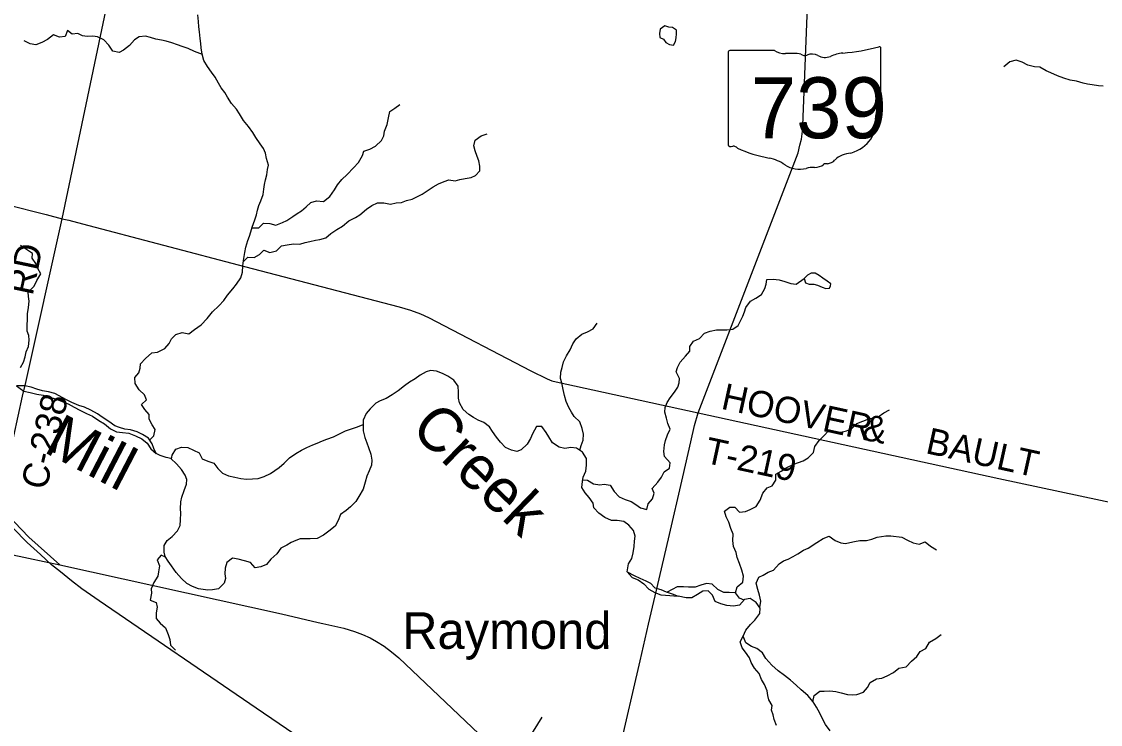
# Model space of a CAD drawing. Extents: x 0 to 34, y 0 to 22.
# Drawn here: x 4.289 to 5.454, y 16.008 to 16.767 of the extents above; entities that cross this region are included whole.
import ezdxf

# ---------------------------------------------------------------- set-up
doc = ezdxf.new("R2010")
doc.units = 0
for name, color, linetype in [('GM_X_County_Road', 7, 'Continuous'), ('GM_X_County_Road_Text', 7, 'Continuous'), ('GM_X_Minor_Lake', 7, 'Continuous'), ('GM_X_Minor_River', 7, 'Continuous'), ('GM_X_Minor_River_Text', 7, 'Continuous'), ('GM_X_Rail_Line', 7, 'Continuous'), ('GM_X_State_Location', 7, 'Continuous'), ('GM_X_State_Route', 7, 'Continuous'), ('GM_X_State_Shield', 7, 'Continuous'), ('GM_X_Township_Road', 7, 'Continuous'), ('GM_X_Township_Road_Text', 7, 'Continuous'), ('GM_X_Unincorporated_Text', 7, 'Continuous')]:
    doc.layers.add(name, color=color, linetype=linetype)

msp = doc.modelspace()

# ---------------------------------------------------------------- linework, layer by layer
at = {"layer": 'GM_X_County_Road'}
msp.add_line((4.2903, 16.3625), (4.2936, 16.3773), dxfattribs=at)
for points in [[(4.2936, 16.3773), (4.333, 16.5543), (4.4295, 17.0147), (4.5014, 17.3574)], [(4.2728, 16.5698), (4.3156, 16.5588), (4.333, 16.5543), (4.3403, 16.5528), (4.3548, 16.5489), (4.5299, 16.5028), (4.697, 16.459), (4.7091, 16.4555), (4.7198, 16.4517), (4.7285, 16.4476), (4.8392, 16.3899), (4.8569, 16.3811), (4.8619, 16.3792), (4.8666, 16.3781), (5.02, 16.3446)], [(4.3303, 16.1801), (4.2971, 16.2101), (4.2816, 16.2262), (4.2729, 16.236), (4.2689, 16.2412), (4.2665, 16.2462), (4.2657, 16.2525), (4.2662, 16.2589), (4.2807, 16.3193), (4.2903, 16.3625)]]:
    msp.add_lwpolyline(points, dxfattribs=at)
at = {"layer": 'GM_X_Minor_Lake'}
for points in [[(4.9787, 16.7593), (4.9781, 16.7547), (4.9785, 16.7504), (4.9824, 16.7486), (4.9849, 16.7448), (4.989, 16.7426), (4.9932, 16.7418), (4.9955, 16.7458), (4.9961, 16.7497), (4.9965, 16.7541), (4.9965, 16.7556)], [(4.9965, 16.7556), (4.9965, 16.7581), (4.9921, 16.7609), (4.988, 16.7615), (4.9838, 16.7629), (4.9787, 16.7593)], [(5.1626, 16.4819), (5.1632, 16.4838), (5.1593, 16.4867), (5.1544, 16.4901), (5.1506, 16.4931), (5.1462, 16.4956), (5.1419, 16.4954), (5.1379, 16.4932), (5.1343, 16.4896)], [(5.1343, 16.4896), (5.1358, 16.4852), (5.1398, 16.4837), (5.1447, 16.4837), (5.1487, 16.4825), (5.1536, 16.4802), (5.1577, 16.4789), (5.1617, 16.4794), (5.1626, 16.4819)]]:
    msp.add_lwpolyline(points, dxfattribs=at)
at = {"layer": 'GM_X_Minor_River'}
for points in [[(4.4274, 16.3151), (4.432, 16.3198), (4.4335, 16.3264), (4.4301, 16.3315), (4.4271, 16.3378), (4.4269, 16.3427), (4.4224, 16.3481), (4.4187, 16.3536), (4.4242, 16.3587), (4.4219, 16.3638), (4.4163, 16.3693), (4.4119, 16.3762), (4.4114, 16.3826), (4.4156, 16.3879), (4.4171, 16.3927), (4.4177, 16.3974), (4.4228, 16.4034), (4.4297, 16.4095), (4.4361, 16.41), (4.4437, 16.414), (4.4486, 16.4195), (4.4509, 16.4244), (4.4557, 16.4291), (4.4627, 16.4312), (4.4697, 16.4298), (4.4758, 16.4347), (4.4832, 16.4396), (4.4897, 16.4464), (4.4952, 16.4538), (4.502, 16.4601), (4.5076, 16.4661), (4.5116, 16.4716), (4.5173, 16.4786), (4.5213, 16.4835), (4.5258, 16.4903), (4.5276, 16.4967), (4.528, 16.5034), (4.5288, 16.5093), (4.5301, 16.5178), (4.5315, 16.5237), (4.5336, 16.5309), (4.5353, 16.5356), (4.5366, 16.5403), (4.5382, 16.5453), (4.5412, 16.5532), (4.543, 16.5587), (4.5439, 16.5636), (4.5455, 16.5686), (4.5476, 16.5735), (4.5499, 16.5807), (4.5508, 16.5864), (4.5516, 16.5915), (4.5524, 16.5964), (4.5539, 16.6019), (4.5549, 16.6074), (4.5557, 16.6123), (4.5538, 16.6194), (4.5525, 16.6252), (4.5504, 16.6304), (4.5467, 16.6353), (4.5421, 16.642), (4.539, 16.6475), (4.5342, 16.654), (4.5288, 16.6606), (4.5246, 16.6676), (4.5211, 16.6726), (4.5158, 16.6789), (4.5114, 16.6857), (4.5086, 16.6907), (4.5047, 16.6958), (4.5018, 16.7009), (4.4983, 16.7072), (4.4941, 16.7127), (4.49, 16.7188), (4.4858, 16.7254), (4.4843, 16.7323), (4.4832, 16.7391), (4.4829, 16.7439), (4.4821, 16.7492), (4.4812, 16.7562), (4.4805, 16.7619), (4.4801, 16.7674), (4.4796, 16.7746)], [(4.4845, 16.7317), (4.476, 16.7352), (4.469, 16.7382), (4.4626, 16.7405), (4.4575, 16.7422), (4.4514, 16.7445), (4.4454, 16.7463), (4.4401, 16.7472), (4.4342, 16.7484), (4.4283, 16.7501), (4.4229, 16.7515), (4.416, 16.7509), (4.4111, 16.7477), (4.4056, 16.7415), (4.3991, 16.7366), (4.3944, 16.7341), (4.3876, 16.7355), (4.3834, 16.7418), (4.3778, 16.7477), (4.3713, 16.7511), (4.366, 16.7517), (4.3598, 16.7513), (4.3549, 16.7519), (4.3499, 16.7544), (4.3439, 16.7537), (4.3388, 16.7579), (4.3361, 16.7514), (4.3302, 16.7507), (4.3236, 16.7532), (4.3171, 16.7481), (4.3109, 16.7447), (4.3044, 16.7424), (4.2984, 16.7434), (4.2921, 16.7465)], [(5.4573, 16.6975), (5.4524, 16.6979), (5.4454, 16.6991), (5.4405, 16.6998), (5.4355, 16.7008), (5.4285, 16.7029), (5.4217, 16.7041), (5.4147, 16.7064), (5.4081, 16.7089), (5.4007, 16.7119), (5.3956, 16.7142), (5.3888, 16.7182), (5.383, 16.7184), (5.376, 16.7203), (5.3697, 16.7234), (5.3633, 16.7259), (5.3565, 16.724), (5.35, 16.7185)], [(4.5379, 16.5444), (4.5452, 16.5445), (4.5503, 16.5494), (4.5571, 16.549), (4.5639, 16.5473), (4.571, 16.5503), (4.5757, 16.5523), (4.582, 16.5567), (4.5867, 16.5599), (4.5915, 16.5627), (4.5964, 16.5672), (4.6015, 16.572), (4.6078, 16.5736), (4.6152, 16.573), (4.6222, 16.5783), (4.6272, 16.5855), (4.6302, 16.591), (4.635, 16.5969), (4.6407, 16.6023), (4.6477, 16.6095), (4.6531, 16.6152), (4.6574, 16.6226), (4.6586, 16.6275), (4.6654, 16.6294), (4.6715, 16.6328), (4.6778, 16.639), (4.6804, 16.6441), (4.6812, 16.649), (4.6841, 16.6562), (4.6854, 16.6634), (4.6868, 16.6701), (4.6921, 16.6738), (4.6978, 16.6778)], [(4.5285, 16.5077), (4.5335, 16.5127), (4.5403, 16.5124), (4.5462, 16.5155), (4.5508, 16.5204), (4.5574, 16.5177), (4.5644, 16.5196), (4.5697, 16.5252), (4.5758, 16.5262), (4.5828, 16.5271), (4.5896, 16.5269), (4.5955, 16.5287), (4.6004, 16.5299), (4.6065, 16.5312), (4.6112, 16.5319), (4.6177, 16.5336), (4.6232, 16.5385), (4.6297, 16.5428), (4.6357, 16.5462), (4.6426, 16.5519), (4.6496, 16.5555), (4.6543, 16.5587), (4.6616, 16.5645), (4.6673, 16.5687), (4.6735, 16.5715), (4.6803, 16.5715), (4.6874, 16.5701), (4.6938, 16.5714), (4.6993, 16.572), (4.7048, 16.5739), (4.7111, 16.5753), (4.7169, 16.5782), (4.7217, 16.581), (4.7281, 16.5851), (4.7336, 16.5889), (4.7393, 16.5919), (4.7456, 16.5946), (4.7507, 16.5963), (4.7575, 16.5953), (4.7623, 16.5968), (4.7683, 16.5977), (4.7746, 16.599), (4.7795, 16.6009), (4.7841, 16.606), (4.7841, 16.6111), (4.7828, 16.6168), (4.7813, 16.6216), (4.7789, 16.6278), (4.7774, 16.6331), (4.7789, 16.6394), (4.7854, 16.6439), (4.7918, 16.646)], [(4.2881, 16.3935), (4.2912, 16.3992), (4.2929, 16.4051), (4.294, 16.4104), (4.2965, 16.4164), (4.2975, 16.4231), (4.2968, 16.428), (4.2951, 16.4327), (4.2953, 16.4388), (4.2957, 16.4456), (4.2955, 16.4517), (4.2965, 16.4585), (4.2975, 16.4654), (4.2967, 16.4701), (4.2964, 16.475), (4.3028, 16.4815), (4.3057, 16.4877), (4.3101, 16.4949), (4.3067, 16.5006), (4.3045, 16.5061), (4.3005, 16.5116), (4.3011, 16.5166), (4.288, 16.5253)], [(4.8952, 16.2721), (4.9004, 16.2718), (4.9067, 16.2679), (4.9135, 16.2668), (4.9184, 16.2675), (4.9247, 16.2662), (4.9292, 16.2595), (4.9345, 16.2538), (4.9409, 16.2509), (4.9475, 16.2488), (4.9526, 16.2454), (4.9577, 16.2418), (4.9643, 16.2399), (4.9657, 16.2461), (4.9706, 16.2516), (4.9722, 16.2578), (4.9703, 16.2628), (4.9762, 16.2694), (4.9802, 16.2751), (4.9831, 16.2809), (4.9888, 16.2847), (4.9895, 16.2904), (4.9835, 16.2973), (4.9828, 16.3028), (4.9836, 16.3098), (4.9847, 16.3145), (4.9866, 16.3206), (4.9895, 16.3268), (4.9871, 16.3329), (4.9858, 16.3388), (4.9837, 16.3452), (4.9841, 16.3504), (4.9862, 16.3558), (4.9896, 16.3608), (4.9942, 16.367), (4.9978, 16.3721), (4.9994, 16.3769), (4.9996, 16.3818), (4.9962, 16.3888), (4.9975, 16.3937), (5.0004, 16.3992), (5.0061, 16.4057), (5.0107, 16.4113), (5.0107, 16.4163), (5.0149, 16.4219), (5.0213, 16.4249), (5.0268, 16.4308), (5.0329, 16.4329), (5.0395, 16.4342), (5.0443, 16.4343), (5.0507, 16.4341), (5.0574, 16.4349), (5.0631, 16.439), (5.0657, 16.4439), (5.0682, 16.4491), (5.0699, 16.4538), (5.0713, 16.4585), (5.0764, 16.4651), (5.0823, 16.4683), (5.0882, 16.4725), (5.092, 16.4789), (5.0932, 16.4837), (5.0941, 16.4888), (5.1009, 16.4891), (5.1072, 16.4882), (5.1134, 16.4864), (5.1201, 16.4843), (5.1257, 16.4837), (5.1343, 16.4896)], [(4.8919, 16.3041), (4.8936, 16.3092), (4.8957, 16.3148), (4.8959, 16.3215), (4.8944, 16.3277), (4.8922, 16.3348), (4.8861, 16.3407), (4.8831, 16.3454), (4.8803, 16.3502), (4.8773, 16.3568), (4.8754, 16.3633), (4.8741, 16.3699), (4.8726, 16.3769), (4.8713, 16.3817), (4.8717, 16.3885), (4.8731, 16.3934), (4.8744, 16.3997), (4.8778, 16.4061), (4.8815, 16.4127), (4.8845, 16.4192), (4.888, 16.4245), (4.8942, 16.4294), (4.9005, 16.432), (4.9064, 16.4354), (4.9108, 16.4413)], [(4.9432, 16.1726), (4.9445, 16.1812), (4.9482, 16.1871), (4.9495, 16.1933), (4.9507, 16.1999), (4.9511, 16.2058), (4.9517, 16.2111), (4.9499, 16.2172), (4.945, 16.2231), (4.9395, 16.2269), (4.9325, 16.2281), (4.9261, 16.2281), (4.9189, 16.2314), (4.9127, 16.2362), (4.9072, 16.2419), (4.9063, 16.2468), (4.9021, 16.2531), (4.8978, 16.2579), (4.8943, 16.2638), (4.8949, 16.2702), (4.8956, 16.2751), (4.8985, 16.2816), (4.8993, 16.288), (4.8992, 16.2952), (4.895, 16.3019), (4.8886, 16.3063), (4.8824, 16.3069), (4.8759, 16.3058), (4.8697, 16.3075), (4.8625, 16.3121), (4.8584, 16.3184), (4.8556, 16.3232), (4.8509, 16.3296), (4.8452, 16.3297), (4.841, 16.3217), (4.8389, 16.3168), (4.8352, 16.3106), (4.8288, 16.3047), (4.824, 16.3028), (4.8181, 16.304), (4.8119, 16.3071), (4.8065, 16.3128), (4.8021, 16.3181), (4.7976, 16.3244), (4.7944, 16.3294), (4.7882, 16.334), (4.7822, 16.3365), (4.7772, 16.3393), (4.7723, 16.3426), (4.7659, 16.3481), (4.7622, 16.3555), (4.7611, 16.3605), (4.7609, 16.3667), (4.7606, 16.3734), (4.7561, 16.3798), (4.7495, 16.384), (4.7436, 16.3871), (4.7374, 16.3896), (4.7309, 16.3904), (4.7262, 16.3887), (4.7195, 16.3852), (4.7142, 16.3812), (4.7081, 16.3776), (4.7028, 16.3737), (4.696, 16.3684), (4.6893, 16.3641), (4.683, 16.3601), (4.6764, 16.3575), (4.6716, 16.3551), (4.6655, 16.349), (4.6614, 16.3439), (4.6581, 16.3367), (4.6581, 16.3305), (4.6582, 16.3252), (4.6597, 16.318), (4.6619, 16.3121), (4.6638, 16.3069), (4.6664, 16.2999), (4.6673, 16.2935), (4.6671, 16.288), (4.6646, 16.2819), (4.6619, 16.276), (4.6602, 16.2696), (4.6579, 16.262), (4.6533, 16.2541), (4.65, 16.2488), (4.6445, 16.2428), (4.6397, 16.239), (4.6336, 16.2345), (4.6311, 16.228), (4.6277, 16.222), (4.6209, 16.2165), (4.6153, 16.2124), (4.6085, 16.2088), (4.6009, 16.2083), (4.5951, 16.2085), (4.5901, 16.2082), (4.5852, 16.2067), (4.5804, 16.2044), (4.5757, 16.2014), (4.5692, 16.1984)], [(4.2837, 16.3737), (4.2916, 16.3678), (4.2984, 16.3664), (4.3056, 16.3647), (4.3126, 16.3635), (4.3194, 16.3616), (4.3256, 16.3596), (4.3328, 16.3569), (4.3394, 16.3542), (4.346, 16.3508), (4.3521, 16.3473), (4.3592, 16.3439), (4.3657, 16.3408), (4.3725, 16.3364), (4.3787, 16.3326), (4.3853, 16.3271), (4.3917, 16.324), (4.3981, 16.3232), (4.405, 16.3226), (4.4121, 16.3197), (4.4189, 16.3164), (4.4246, 16.3117), (4.4289, 16.3056), (4.4344, 16.3006)], [(4.4344, 16.3006), (4.4321, 16.3061), (4.4301, 16.3109), (4.4261, 16.317), (4.4199, 16.3212), (4.4139, 16.3241), (4.4069, 16.326), (4.4008, 16.3268), (4.395, 16.3285), (4.39, 16.3304), (4.3833, 16.335), (4.3763, 16.3398), (4.3712, 16.3434), (4.364, 16.3473), (4.3572, 16.3505), (4.351, 16.3525), (4.3434, 16.3557), (4.3368, 16.3588), (4.3298, 16.3628), (4.3249, 16.3653), (4.3183, 16.3671), (4.3118, 16.3684), (4.3056, 16.37), (4.2994, 16.3721), (4.2927, 16.3737), (4.2837, 16.3737)], [(5.0695, 16.1422), (5.0644, 16.1441), (5.06, 16.15), (5.0618, 16.1564), (5.068, 16.1615), (5.0688, 16.168), (5.067, 16.1744), (5.0645, 16.1817), (5.0621, 16.1881), (5.0608, 16.1934), (5.058, 16.2001), (5.0572, 16.2067), (5.0578, 16.2135), (5.0552, 16.2194), (5.0531, 16.2265), (5.0501, 16.232), (5.0484, 16.2382), (5.054, 16.2424), (5.0595, 16.2426), (5.0645, 16.2372), (5.071, 16.238), (5.0759, 16.24), (5.0826, 16.2432), (5.0869, 16.2502), (5.0898, 16.2576), (5.0944, 16.2633), (5.0999, 16.2655), (5.1037, 16.2718), (5.1037, 16.2782), (5.1094, 16.2816), (5.1157, 16.2854), (5.1231, 16.289), (5.1282, 16.2909), (5.1331, 16.2927), (5.1388, 16.2959), (5.1444, 16.3016), (5.1459, 16.3081), (5.1505, 16.3145), (5.1554, 16.3196), (5.1607, 16.3251), (5.1674, 16.3245), (5.1738, 16.3235), (5.1802, 16.325), (5.1854, 16.3274), (5.1913, 16.3329), (5.1977, 16.3356), (5.2025, 16.3373), (5.2078, 16.3388), (5.2144, 16.3402), (5.2203, 16.3446), (5.2266, 16.3478)], [(4.4511, 16.2943), (4.4516, 16.2988), (4.4556, 16.3053), (4.462, 16.3073), (4.4687, 16.3069), (4.4749, 16.3042), (4.4811, 16.3012), (4.484, 16.2947), (4.4902, 16.2922), (4.4968, 16.2901), (4.5012, 16.2842), (4.5061, 16.2793), (4.5127, 16.2764), (4.5195, 16.2749), (4.5259, 16.2735), (4.5322, 16.2727), (4.5386, 16.2731), (4.5445, 16.2736), (4.5511, 16.2757), (4.5578, 16.2791), (4.5627, 16.2821), (4.5675, 16.2855), (4.5728, 16.2902), (4.5785, 16.2957), (4.5855, 16.3006), (4.5916, 16.304), (4.5971, 16.307), (4.6036, 16.31), (4.6085, 16.3117), (4.614, 16.3142), (4.6189, 16.316), (4.6259, 16.3187), (4.6318, 16.3215), (4.639, 16.3249), (4.6453, 16.3273), (4.6519, 16.3294), (4.6581, 16.3319)], [(4.5692, 16.1984), (4.5647, 16.192), (4.5584, 16.1862), (4.5536, 16.1807), (4.5477, 16.1781), (4.5415, 16.177), (4.5364, 16.1829), (4.5299, 16.1846), (4.5229, 16.1862), (4.5169, 16.1875), (4.5108, 16.1828), (4.5089, 16.1766), (4.5088, 16.1705), (4.5092, 16.1654), (4.508, 16.1605), (4.5019, 16.1542), (4.4953, 16.1531), (4.4902, 16.153), (4.4853, 16.1536), (4.4803, 16.1543), (4.4737, 16.1568), (4.4675, 16.1599), (4.4618, 16.1653), (4.4562, 16.1719), (4.4509, 16.1792), (4.4474, 16.1841), (4.4442, 16.1891), (4.4431, 16.1938), (4.4433, 16.201), (4.4464, 16.2065), (4.4519, 16.2108), (4.4574, 16.2169), (4.4605, 16.2229), (4.4609, 16.229), (4.4611, 16.2362), (4.4608, 16.2409), (4.4612, 16.2483), (4.4621, 16.2532), (4.4647, 16.2604), (4.4673, 16.2674), (4.4676, 16.2724), (4.4657, 16.2773), (4.4619, 16.2832), (4.4565, 16.2895), (4.4503, 16.295), (4.4453, 16.2962), (4.4389, 16.2985), (4.4344, 16.3006)], [(5.0864, 16.134), (5.0875, 16.141), (5.0862, 16.1474), (5.0843, 16.1537), (5.0824, 16.1603), (5.0855, 16.167), (5.0902, 16.169), (5.0954, 16.1724), (5.1012, 16.1745), (5.1073, 16.1813), (5.1121, 16.1845), (5.1172, 16.1862), (5.1225, 16.1892), (5.1275, 16.192), (5.1337, 16.196), (5.1385, 16.1983), (5.148, 16.2043), (5.155, 16.2086), (5.1614, 16.2111), (5.1679, 16.2067), (5.1739, 16.204), (5.1788, 16.2034), (5.1836, 16.2042), (5.1887, 16.2053), (5.1946, 16.2064), (5.2016, 16.2064), (5.2073, 16.2081), (5.213, 16.2101), (5.2177, 16.2109), (5.2224, 16.2114), (5.2279, 16.2114), (5.2399, 16.2101), (5.2461, 16.2068), (5.252, 16.2039), (5.2586, 16.2024), (5.265, 16.205), (5.2707, 16.2003), (5.2773, 16.1966)], [(4.4446, 16.1884), (4.44, 16.1908), (4.4354, 16.1857), (4.4381, 16.1792), (4.4369, 16.1728), (4.4363, 16.1678), (4.4319, 16.161), (4.4291, 16.1544), (4.4294, 16.1495), (4.4279, 16.1421), (4.4345, 16.1394), (4.4356, 16.1346), (4.4344, 16.1284), (4.4344, 16.1223), (4.4388, 16.1172), (4.4446, 16.1122), (4.4476, 16.105), (4.4493, 16.0995), (4.4498, 16.0934), (4.4553, 16.0879)], [(4.9432, 16.1726), (4.9486, 16.1666), (4.9549, 16.1639), (4.9611, 16.1597), (4.9664, 16.154), (4.9732, 16.1503), (4.9796, 16.1478), (4.9845, 16.1476), (4.9981, 16.1462)], [(4.9432, 16.1726), (4.9507, 16.1688), (4.957, 16.1658), (4.9634, 16.1631), (4.9683, 16.1604), (4.9732, 16.1554), (4.9794, 16.1535), (4.9853, 16.1512), (4.9919, 16.1487), (4.9981, 16.1462)], [(5.0602, 16.1498), (5.0532, 16.1504), (5.0475, 16.1502), (5.0411, 16.1537), (5.0349, 16.1592), (5.0288, 16.16), (5.0226, 16.1581), (5.0165, 16.156), (5.0093, 16.1561), (5.004, 16.1565), (4.9972, 16.1563), (4.9863, 16.1508)], [(5.1044, 16.0066), (5.102, 16.0131), (5.1008, 16.018), (5.099, 16.0232), (5.0996, 16.0281), (5.096, 16.0342), (5.0951, 16.0389), (5.0944, 16.044), (5.0916, 16.0509), (5.0884, 16.0564), (5.0856, 16.0629), (5.0807, 16.0686), (5.0771, 16.0745), (5.0752, 16.0798), (5.0711, 16.0857), (5.0673, 16.0905), (5.0651, 16.0969), (5.0686, 16.103), (5.0714, 16.1096), (5.0764, 16.1158), (5.0812, 16.1205), (5.0863, 16.1275), (5.0869, 16.1332), (5.0826, 16.1395), (5.076, 16.1439), (5.0699, 16.1426), (5.0646, 16.1367), (5.0579, 16.1355), (5.0509, 16.1361), (5.0443, 16.138), (5.0381, 16.1407), (5.0355, 16.1475), (5.0306, 16.1521), (5.0249, 16.1516), (5.019, 16.1482), (5.0129, 16.1446), (5.0068, 16.1445), (4.9981, 16.1462)], [(5.1625, 16.0007), (5.1572, 16.0078), (5.1546, 16.0131), (5.1514, 16.0199), (5.1478, 16.0262), (5.1439, 16.0321), (5.1382, 16.0388), (5.1312, 16.045), (5.1258, 16.05), (5.1195, 16.0557), (5.1131, 16.0607), (5.1061, 16.0656), (5.0993, 16.0717), (5.0931, 16.0788), (5.0895, 16.0852), (5.0833, 16.0898), (5.0774, 16.0921), (5.0712, 16.0959), (5.0686, 16.1031)], [(5.1437, 16.0323), (5.1452, 16.0389), (5.1511, 16.0435), (5.1559, 16.0438), (5.1621, 16.0442), (5.1687, 16.0432), (5.1744, 16.0417), (5.1812, 16.0401), (5.1862, 16.0397), (5.1911, 16.0401), (5.1985, 16.0427), (5.2027, 16.0478), (5.2055, 16.0531), (5.2124, 16.0569), (5.2182, 16.0578), (5.2239, 16.0601), (5.2308, 16.064), (5.2367, 16.0684), (5.2444, 16.0701), (5.2503, 16.0761), (5.256, 16.0812), (5.2597, 16.0867), (5.2659, 16.0897), (5.2697, 16.0965), (5.2764, 16.1005), (5.2823, 16.1048)]]:
    msp.add_lwpolyline(points, dxfattribs=at)
at = {"layer": 'GM_X_Rail_Line'}
msp.add_lwpolyline([(4.6001, 15.986), (4.5426, 16.0253), (4.373, 16.1412), (4.3542, 16.1544), (4.3431, 16.1628), (4.3312, 16.1725), (4.3213, 16.1802), (4.3095, 16.1915), (4.295, 16.2045), (4.28, 16.2198)], dxfattribs=at)
at = {"layer": 'GM_X_State_Route'}
for points in [[(4.9877, 16.2084), (5.0033, 16.2754), (5.0119, 16.3131), (5.016, 16.3308), (5.02, 16.3446), (5.1277, 16.6254), (5.1298, 16.6339), (5.1314, 16.6405), (5.1326, 16.649), (5.133, 16.6551), (5.1459, 16.9851)], [(4.9663, 16.116), (4.9762, 16.1589), (4.9877, 16.2084)], [(4.2797, 16.1912), (4.3303, 16.1801), (4.57, 16.1271), (4.6096, 16.118)], [(4.6096, 16.118), (4.6144, 16.1168), (4.6373, 16.1116), (4.6488, 16.1081), (4.6575, 16.1049), (4.6656, 16.1012), (4.6726, 16.0974), (4.6809, 16.0922), (4.6888, 16.0863), (4.6964, 16.0798), (4.7903, 15.9907), (4.8025, 15.9792), (4.817, 15.9653)], [(4.9304, 15.9603), (4.9345, 15.9783), (4.9571, 16.0764), (4.9663, 16.116)]]:
    msp.add_lwpolyline(points, dxfattribs=at)
at = {"layer": 'GM_X_State_Shield'}
for p, q in [((5.0523, 16.7343), (5.0523, 16.6343)), ((5.1022, 16.7361), (5.054, 16.7361)), ((5.2171, 16.6862), (5.2171, 16.7385)), ((5.2171, 16.6862), (5.2171, 16.6862))]:
    msp.add_line(p, q, dxfattribs=at)
for centre, major_axis, start_param, end_param in [((5.0542, 16.7345), (0.00191, 0), 1.712693, 3.28349), ((5.1137, 16.7477), (0.0185, 0), 4.042523, 4.731795), ((5.1199, 16.6799), (0.0665, 0), 1.404758, 1.657858), ((5.135, 16.7351), (0.00534, 0), 3.836095, 5.185415), ((5.1428, 16.7235), (0.0111, 0), 0.950623, 2.079405), ((5.1807, 16.7055), (0.0352, 0), 1.699011, 2.107814), ((5.1584, 16.8725), (0.1748, 0), 4.814394, 5.042369), ((5.2153, 16.7388), (0.00183, 0), 6.141152, 7.989035), ((5.1571, 16.7394), (0.0134, 0), 4.081561, 5.145723), ((5.2152, 16.686), (0.00196, 0), 5.05454, 6.418171), ((5.2167, 16.6824), (0.00284, 0), 1.883978, 3.671073), ((5.1987, 16.6757), (0.017, 0), 5.934695, 6.695948), ((5.1682, 16.6576), (0.0437, 0), 5.101752, 6.440018), ((5.2237, 16.6643), (0.0124, 0), 2.387724, 3.262537), ((5.0543, 16.6341), (0.00193, 0), 3.00124, 4.508301), ((5.0545, 16.6443), (0.0147, 0), 4.665946, 4.897461), ((5.0576, 16.6285), (0.0053, 0), 0.519207, 1.627899), ((5.1245, 16.7184), (0.1262, 0), 4.195997, 4.488961), ((5.0868, 16.5893), (0.0395, 0), 0.823519, 1.323587), ((5.1563, 16.6246), (0.0141, 0), 4.937069, 5.64225), ((5.1867, 16.6062), (0.0239, 0), 1.647645, 2.488434), ((5.1295, 16.628), (0.0251, 0), 4.026481, 4.996735), ((5.144, 16.5934), (0.0206, 0), 1.495662, 1.94098), ((5.1459, 16.6205), (0.0133, 0), 4.691044, 5.507374), ((5.1579, 16.6108), (0.00376, 0), 1.147584, 2.315152)]:
    msp.add_ellipse(centre, major_axis=major_axis, ratio=0.8, start_param=start_param, end_param=end_param, dxfattribs=at)
at = {"layer": 'GM_X_Township_Road'}
for points in [[(5.02, 16.3446), (5.3446, 16.2737), (5.5694, 16.2257)], [(4.8294, 15.9788), (4.8299, 15.9819), (4.8356, 15.99), (4.8513, 16.0154)]]:
    msp.add_lwpolyline(points, dxfattribs=at)

# ---------------------------------------------------------------- texts
at = {"layer": 'GM_X_County_Road_Text'}
for s, rotation, p in [('RD', 78.1102, (4.301, 16.4704)), ('C-238', 76.6964, (4.3158, 16.2601))]:
    msp.add_text(s, height=0.02841, rotation=rotation, dxfattribs=at).set_placement(p)
at = {"layer": 'GM_X_Minor_River_Text'}
for s, rotation, p in [('Creek', 315.9274, (4.7078, 16.3258)), ('Mill', 332.5473, (4.3115, 16.3028))]:
    msp.add_text(s, height=0.04735, rotation=rotation, dxfattribs=at).set_placement(p)
at = {"layer": 'GM_X_State_Location'}
for s in ['s', 'r']:
    msp.add_text(s, height=0.0000947, dxfattribs=at).set_placement((5.1329, 16.6777))
msp.add_text('739', height=0.0000947, rotation=0, dxfattribs=at).set_placement((5.0995, 16.6708))
at = {"layer": 'GM_X_State_Shield'}
msp.add_text('739', height=0.06592, dxfattribs=at).set_placement((5.0766, 16.6413))
at = {"layer": 'GM_X_Township_Road_Text'}
for s, height, rotation, p in [('HOOVER', 0.02841, 347.6859, (5.0435, 16.3491)), ('&', 0.0284, 348.5174, (5.1959, 16.3158)), ('BAULT', 0.02841, 347.5609, (5.2644, 16.3011)), ('T-219', 0.02841, 347.8072, (5.0253, 16.2908))]:
    msp.add_text(s, height=height, rotation=rotation, dxfattribs=at).set_placement(p)
at = {"layer": 'GM_X_Unincorporated_Text'}
msp.add_text('Raymond', height=0.03949, rotation=0, dxfattribs=at).set_placement((4.7002, 16.0894))

doc.saveas('drawing.dxf')
